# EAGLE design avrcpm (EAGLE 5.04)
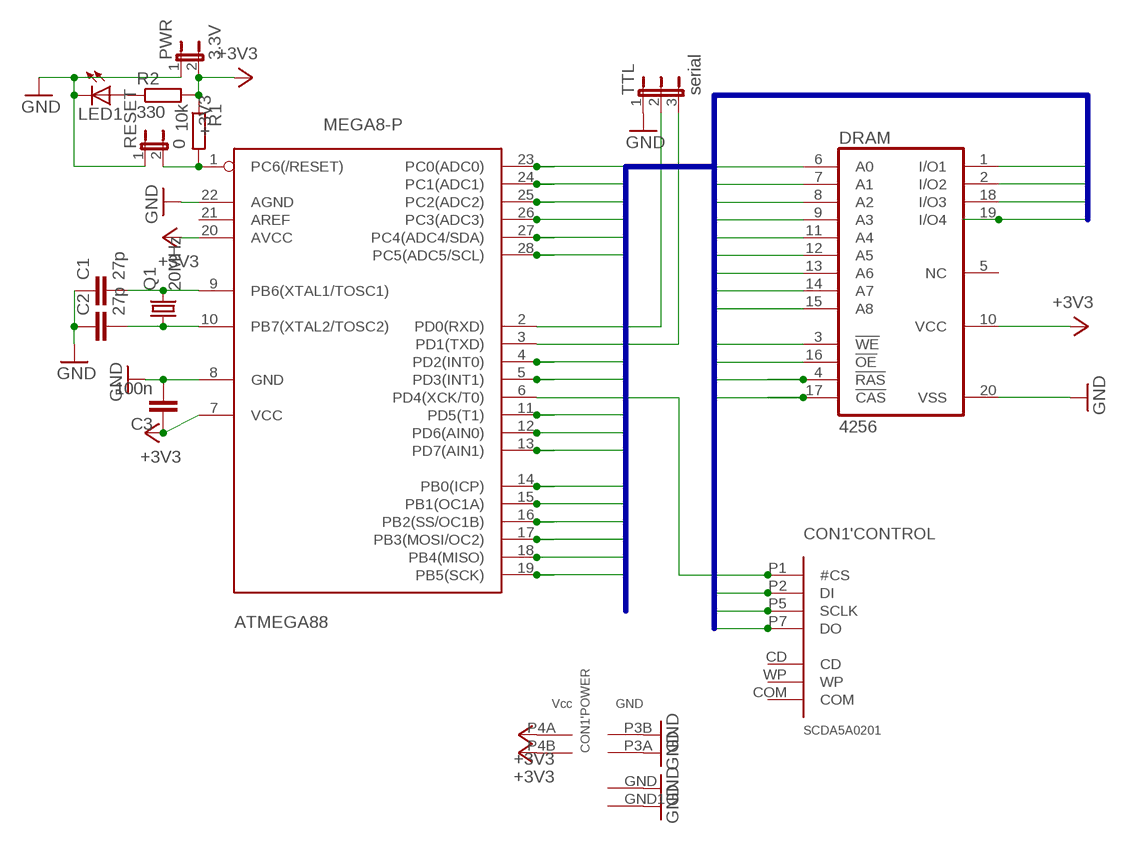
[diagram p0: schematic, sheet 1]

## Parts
ATMEGA88  MEGA8-P  [DIL28-3]
C1  27p  C-EU025-024X044  [C025-024X044]
C2  27p  C-EU025-024X044  [C025-024X044]
C3  100n  C-EU025-024X044  [C025-024X044]
CON1  SCDA5A0201  [SCDA5A0201]
DRAM  4256  514256ALP  [DIL20]
LED1  LED3MM  [LED3MM]
PWR  3.3V  JP1E  [JP1]
Q1  20MHz  CRYSTALHC49U-V  [HC49U-V]
R1  10k  R-EU_0207/7  [0207/7]
R2  330  R-EU_0207/7  [0207/7]
RESET  0  JP1E  [JP1]
TTL  serial  JP2E  [JP2]

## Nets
+3V3: ATMEGA88.7(VCC) ATMEGA88.20(AVCC) C3.1 CON1.P4A('POWER:VCC) CON1.P4B('POWER:VCC1) DRAM.10(VCC) PWR.2 R1.1 R2.2
A0: ATMEGA88.18(PB4(MISO)) CON1.P7('CONTROL:DO) DRAM.6(A0)
A1: ATMEGA88.17(PB3(MOSI/OC2)) CON1.P2('CONTROL:DI) DRAM.7(A1)
A2: ATMEGA88.16(PB2(SS/OC1B)) DRAM.8(A2)
A3: ATMEGA88.15(PB1(OC1A)) DRAM.9(A3)
A4: ATMEGA88.14(PB0(ICP)) DRAM.11(A4)
A5: ATMEGA88.11(PD5(T1)) DRAM.12(A5)
A6: ATMEGA88.12(PD6(AIN0)) DRAM.13(A6)
A7: ATMEGA88.13(PD7(AIN1)) DRAM.14(A7)
A8: ATMEGA88.5(PD3(INT1)) DRAM.15(A8)
CAS: ATMEGA88.28(PC5(ADC5/SCL)) DRAM.17(!CAS)
GND: ATMEGA88.8(GND) ATMEGA88.22(AGND) C1.1 C2.1 C3.2 CON1.GND1('POWER:GND) CON1.GND('POWER:GND) CON1.P3A('POWER:GND) CON1.P3B('POWER:GND) DRAM.20(VSS) LED1.K(C) PWR.1 RESET.1 TTL.1
IO1: ATMEGA88.23(PC0(ADC0)) DRAM.1(I/O1)
IO2: ATMEGA88.25(PC2(ADC2)) DRAM.2(I/O2)
IO3: ATMEGA88.27(PC4(ADC4/SDA)) DRAM.18(I/O3)
IO4: ATMEGA88.26(PC3(ADC3)) DRAM.19(I/O4)
N$1: ATMEGA88.2(PD0(RXD)) TTL.2
N$2: ATMEGA88.3(PD1(TXD)) TTL.3
N$3: ATMEGA88.6(PD4(XCK/T0)) CON1.P1('CONTROL:#CS)
N$4: ATMEGA88.1(PC6(/RESET)) R1.2 RESET.2
N$5: ATMEGA88.10(PB7(XTAL2/TOSC2)) C2.2 Q1.1
N$6: ATMEGA88.9(PB6(XTAL1/TOSC1)) C1.2 Q1.2
N$7: LED1.A R2.1
OE: ATMEGA88.4(PD2(INT0)) DRAM.16(!OE)
RAS: ATMEGA88.19(PB5(SCK)) CON1.P5('CONTROL:SCLK) DRAM.4(!RAS)
WE: ATMEGA88.24(PC1(ADC1)) DRAM.3(!WE)
Unconnected: ATMEGA88.21(AREF) CON1.CD('CONTROL:CD) CON1.COM('CONTROL:COM) CON1.WP('CONTROL:WP) DRAM.5(NC)

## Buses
A[0..8],WE,OE,RAS,CAS,IO[1..4]

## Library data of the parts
ATMEGA88 = atmel:MEGA8-P: MICROCONTROLLER 8 Kbytes FLASH, 1 kbytes SRAM, 512 bytes EEPROM, USART, 4-channel 10 bit ADC, 2-channel 8 bit ADC Pin compatible with Atmega48, ATMega88, ATMega168 Source: avr.lbr
C1-C3 = rcl:C-EU: CAPACITOR, European symbol
CON1 = SCDA5A0201:SCDA5A0201: ALPS Connector for SDMemory Card SD-CARD SCDA5A0201 SPI -MODE
DRAM = memory-hitachi:514256ALP: MEMORY
LED1 = led:LED: LED
PWR RESET = jumper:JP1E: JUMPER
Q1 = crystal:CRYSTAL: CRYSTAL
R1 R2 = rcl:R-EU_: RESISTOR, European symbol
TTL = jumper:JP2E: JUMPER

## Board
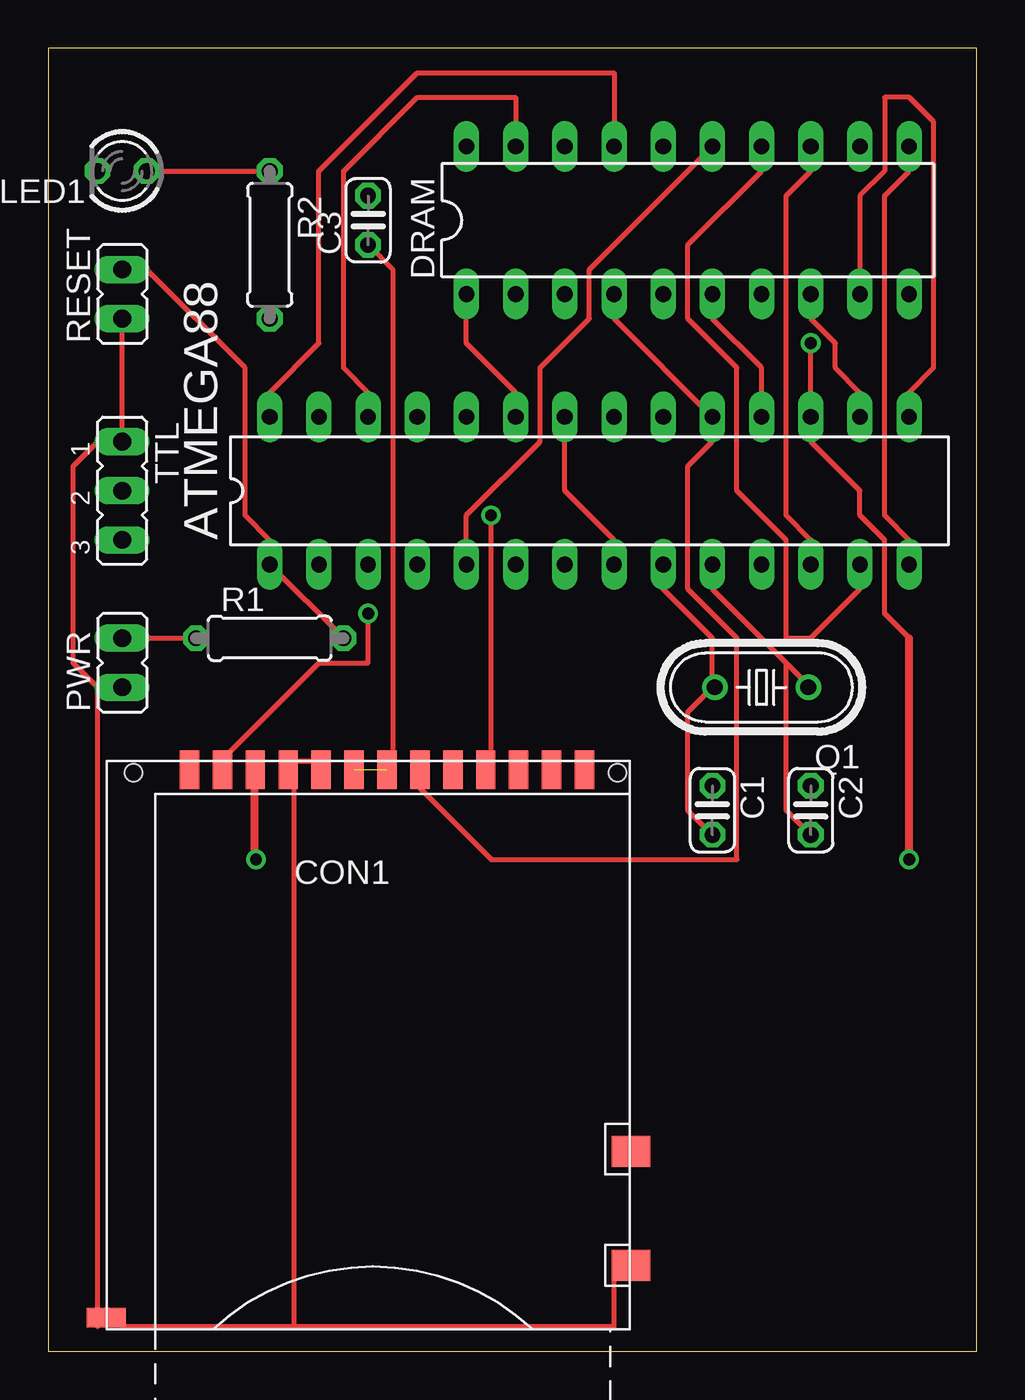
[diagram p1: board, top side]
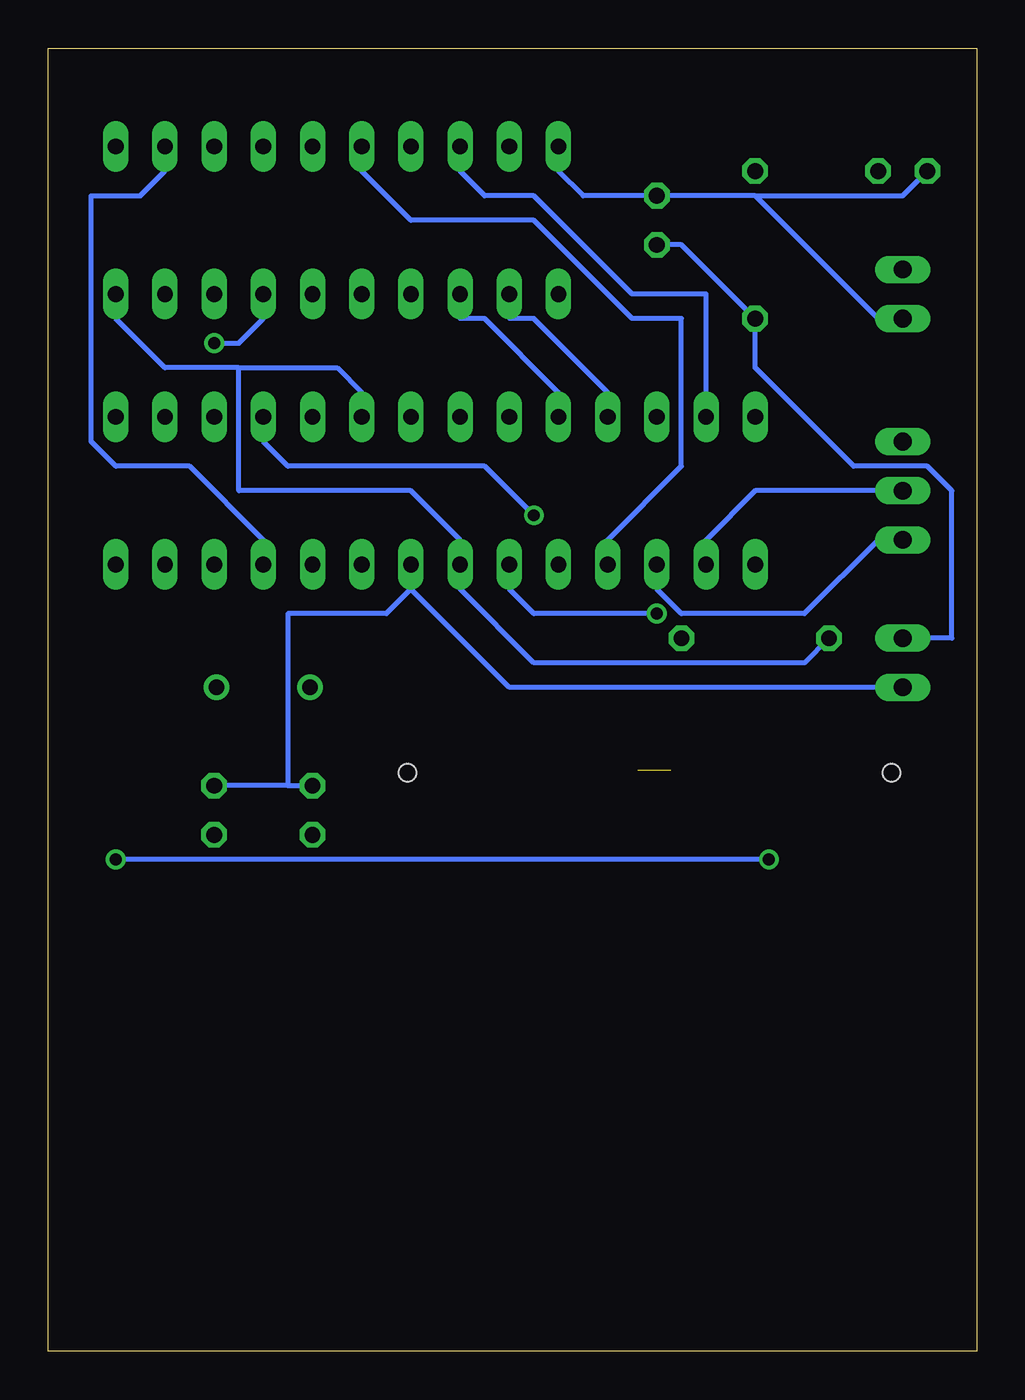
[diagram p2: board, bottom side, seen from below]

Size 47.93 x 67.3 mm. Coordinates in mm from the lower left corner, seen from the top.
Outline: 0,0 47.93,0 47.93,67.3 0,67.3 0,0
Copper layers (1*16): Top 0.035mm / dielectric 1.5mm / Bottom 0.035mm
Design rules "default": minimum track width 10mil, minimum drill 24mil, track to track 8mil, track to pad 8mil, pad to pad 8mil, via to via 8mil, smd to smd 8mil, copper to edge 40mil, drill to drill 8mil, minimum pad ring 10mil, minimum via ring 8mil, stop-mask expansion 4mil, vias tented up to drill 0mil, thermal gap 10mil

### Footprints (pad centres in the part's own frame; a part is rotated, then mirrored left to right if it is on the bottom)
DIL28-3 = drill 0.813 long: 1 -16.51,-3.81; 2 -13.97,-3.81; 3 -11.43,-3.81; 4 -8.89,-3.81; 5 -6.35,-3.81; 6 -3.81,-3.81; 7 -1.27,-3.81; 8 1.27,-3.81; 9 3.81,-3.81; 10 6.35,-3.81; 11 8.89,-3.81; 12 11.43,-3.81; 13 13.97,-3.81; 14 16.51,-3.81; 15 16.51,3.81; 16 13.97,3.81; 17 11.43,3.81; 18 8.89,3.81; 19 6.35,3.81; 20 3.81,3.81; 21 1.27,3.81; 22 -1.27,3.81; 23 -3.81,3.81; 24 -6.35,3.81; 25 -8.89,3.81; 26 -11.43,3.81; 27 -13.97,3.81; 28 -16.51,3.81
C025-024X044 = drill 0.813 octagon: 1 -1.27,0; 2 1.27,0
SCDA5A0201 = smd 1 x 2: CD 9.475,-0.45; COM 11.175,-0.45; P1 -7.525,-0.45; P2 -5.825,-0.45; P3A -4.125,-0.45; P3B -2.425,-0.45; P4A -0.725,-0.45; P4B 0.975,-0.45; P5 2.675,-0.45; P6 4.375,-0.45; P7 6.075,-0.45; P8 7.775,-0.45; P9 -9.225,-0.45 | smd 2 x 1.6: GND 13.575,-26.05; WP 13.575,-20.15 | smd 2 x 1: GND1 -13.525,-28.75 | hole 0.9: -12.125,-0.6; 12.875,-0.6
DIL20 = drill 0.813 long: 1 -11.43,-3.81; 2 -8.89,-3.81; 3 -6.35,-3.81; 4 -3.81,-3.81; 5 -1.27,-3.81; 6 1.27,-3.81; 7 3.81,-3.81; 8 6.35,-3.81; 9 8.89,-3.81; 10 11.43,-3.81; 11 11.43,3.81; 12 8.89,3.81; 13 6.35,3.81; 14 3.81,3.81; 15 1.27,3.81; 16 -1.27,3.81; 17 -3.81,3.81; 18 -6.35,3.81; 19 -8.89,3.81; 20 -11.43,3.81
LED3MM = drill 0.813 octagon: A -1.27,0; K 1.27,0
JP1 = drill 0.914 long: 1 0,-1.27; 2 0,1.27
HC49U-V = drill 0.813 round: 1 -2.413,0; 2 2.413,0
0207/7 = drill 0.813 octagon: 1 -3.81,0; 2 3.81,0
JP2 = drill 0.914 long: 1 -2.54,0; 2 0,0; 3 2.54,0

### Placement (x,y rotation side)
ATMEGA88  27.94,44.45 0 top
C1  34.29,27.94 270 top
C2  39.37,27.94 270 top
C3  16.51,58.42 90 top
CON1  16.51,30.48 0 top
DRAM  33.02,58.42 0 top
LED1  3.81,60.96 180 top
PWR  3.81,35.56 0 top
Q1  36.83,34.29 180 top
R1  11.43,36.83 0 top
R2  11.43,57.15 270 top
RESET  3.81,54.61 0 top
TTL  3.81,44.45 270 top

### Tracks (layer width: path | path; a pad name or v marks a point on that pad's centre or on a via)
+3V3  (1 unrouted)
  Top 0.254: C3.1 17.78,55.88 17.78,30.48 CON1.P4B | PWR.2 R1.1
  Bottom 0.254: C3.1 15.24,57.15 R2.2 11.43,50.8 6.35,45.72 2.54,45.72 1.27,44.45 1.27,36.83 PWR.2 | 38.1,50.8 41.91,50.8 44.45,53.34 DRAM.10 | 38.1,50.8 33.02,50.8 31.75,49.53 ATMEGA88.20 | R1.1 8.89,35.56 22.86,35.56 26.67,39.37 ATMEGA88.7 26.67,41.91 29.21,44.45 38.1,44.45 38.1,50.8
A0  (via drill 0.61)
  Top 0.254: v22.86,43.18 22.86,30.48 CON1.P7 | DRAM.6 34.29,53.34 36.83,50.8 ATMEGA88.18
  Bottom 0.254: v22.86,43.18 25.4,45.72 35.56,45.72 36.83,46.99 ATMEGA88.18
A1  (via drill 0.61)
  Top 0.254: v39.37,52.07 ATMEGA88.17 39.37,46.99 41.91,44.45 41.91,43.18 43.18,41.91 43.18,38.1 44.45,36.83 | v10.72,25.4 10.66,25.4
  Top 0.406: CON1.P2 10.66,30.03 10.66,25.4 | v44.45,25.4 44.45,36.83
  Bottom 0.254: v39.37,52.07 38.1,52.07 36.83,53.34 DRAM.7 | v10.72,25.4 v44.45,25.4
A2
  Top 0.254: ATMEGA88.16 41.91,49.53 40.64,50.8 40.64,52.07 39.37,53.34 DRAM.8
A3
  Top 0.254: ATMEGA88.15 44.45,49.53 45.72,50.8 45.72,63.5 44.45,64.77 43.18,64.77 43.18,60.96 41.91,59.69 DRAM.9
A4
  Top 0.254: ATMEGA88.14 44.45,41.91 43.18,43.18 43.18,59.69 44.45,60.96 DRAM.11
A5
  Bottom 0.254: ATMEGA88.11 36.83,41.91 40.64,45.72 44.45,45.72 45.72,46.99 45.72,59.69 43.18,59.69 41.91,60.96 DRAM.12
A6
  Top 0.254: ATMEGA88.12 39.37,41.91 38.1,43.18 38.1,59.69 39.37,60.96 DRAM.13
A7
  Top 0.254: ATMEGA88.13 41.91,39.37 39.37,36.83 38.1,36.83 38.1,41.91 35.56,44.45 35.56,50.8 33.02,53.34 33.02,57.15 36.83,60.96 DRAM.14
A8
  Top 0.254: DRAM.15 27.94,55.88 27.94,53.34 25.4,50.8 25.4,46.99 21.59,43.18 ATMEGA88.5
CAS
  Top 0.254: ATMEGA88.28 11.43,49.53 13.97,52.07 13.97,60.96 19.05,66.04 29.21,66.04 DRAM.17
GND
  Top 0.254: CON1.P3B 13.97,30.48 12.7,30.48 CON1.P3A 12.7,29.21 12.7,1.27 | 12.7,1.27 29.21,1.27 29.21,3.81 CON1.GND | 12.7,1.27 3.81,1.27 CON1.GND1 2.54,1.27 2.54,34.29 | ATMEGA88.8 29.21,41.91 26.67,44.45 ATMEGA88.22 | 2.54,34.29 1.27,35.56 1.27,45.72 2.54,46.99 TTL.1 RESET.1 | 2.54,34.29 PWR.1
  Bottom 0.254: 35.56,29.21 C2.1 | 35.56,29.21 C1.1 | 35.56,29.21 35.56,38.1 30.48,38.1 29.21,39.37 | LED1.K 3.81,59.69 11.43,59.69 | 11.43,59.69 C3.2 20.32,59.69 21.59,60.96 DRAM.20 | 11.43,59.69 5.08,53.34 RESET.1 | 29.21,39.37 24.13,34.29 PWR.1 | 29.21,39.37 ATMEGA88.8
IO1
  Top 0.254: ATMEGA88.23 24.13,49.53 21.59,52.07 DRAM.1
IO2
  Bottom 0.254: ATMEGA88.25 19.05,49.53 22.86,53.34 24.13,53.34 DRAM.2
IO3
  Bottom 0.254: ATMEGA88.27 13.97,54.61 17.78,54.61 22.86,59.69 25.4,59.69 26.67,60.96 DRAM.18
IO4
  Top 0.254: ATMEGA88.26 16.51,49.53 15.24,50.8 15.24,60.96 19.05,64.77 24.13,64.77 DRAM.19
N$1
  Bottom 0.254: ATMEGA88.2 13.97,41.91 11.43,44.45 TTL.2
N$2
  Bottom 0.254: ATMEGA88.3 16.51,39.37 15.24,38.1 8.89,38.1 5.08,41.91 TTL.3
N$3  (via drill 0.61)
  Top 0.254: v16.51,38.1 16.51,35.56 13.97,35.56 8.89,30.48 CON1.P1
  Bottom 0.254: v16.51,38.1 22.86,38.1 24.13,39.37 ATMEGA88.6
N$4
  Top 0.254: R1.2 ATMEGA88.1 11.43,41.91 10.16,43.18 10.16,50.8 5.08,55.88 RESET.2
N$5
  Top 0.254: 38.1,35.56 34.29,39.37 ATMEGA88.10 | 38.1,35.56 39.37,34.29 Q1.1 | C2.2 38.1,27.94 38.1,35.56
N$6
  Top 0.254: C1.2 33.02,27.94 33.02,33.02 34.29,34.29 | 34.29,34.29 34.29,36.83 31.75,39.37 ATMEGA88.9 | 34.29,34.29 Q1.2
N$7
  Top 0.254: LED1.A R2.1
OE
  Bottom 0.254: ATMEGA88.4 19.05,41.91 15.24,45.72 15.24,53.34 17.78,53.34 22.86,58.42 29.21,58.42 31.75,60.96 DRAM.16
RAS
  Top 0.254: CON1.P5 19.05,29.21 22.86,25.4 35.56,25.4 35.56,36.83 33.02,39.37 33.02,45.72 34.29,46.99 ATMEGA88.19 29.21,53.34 DRAM.4
WE
  Bottom 0.254: ATMEGA88.24 21.59,49.53 25.4,53.34 26.67,53.34 DRAM.3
